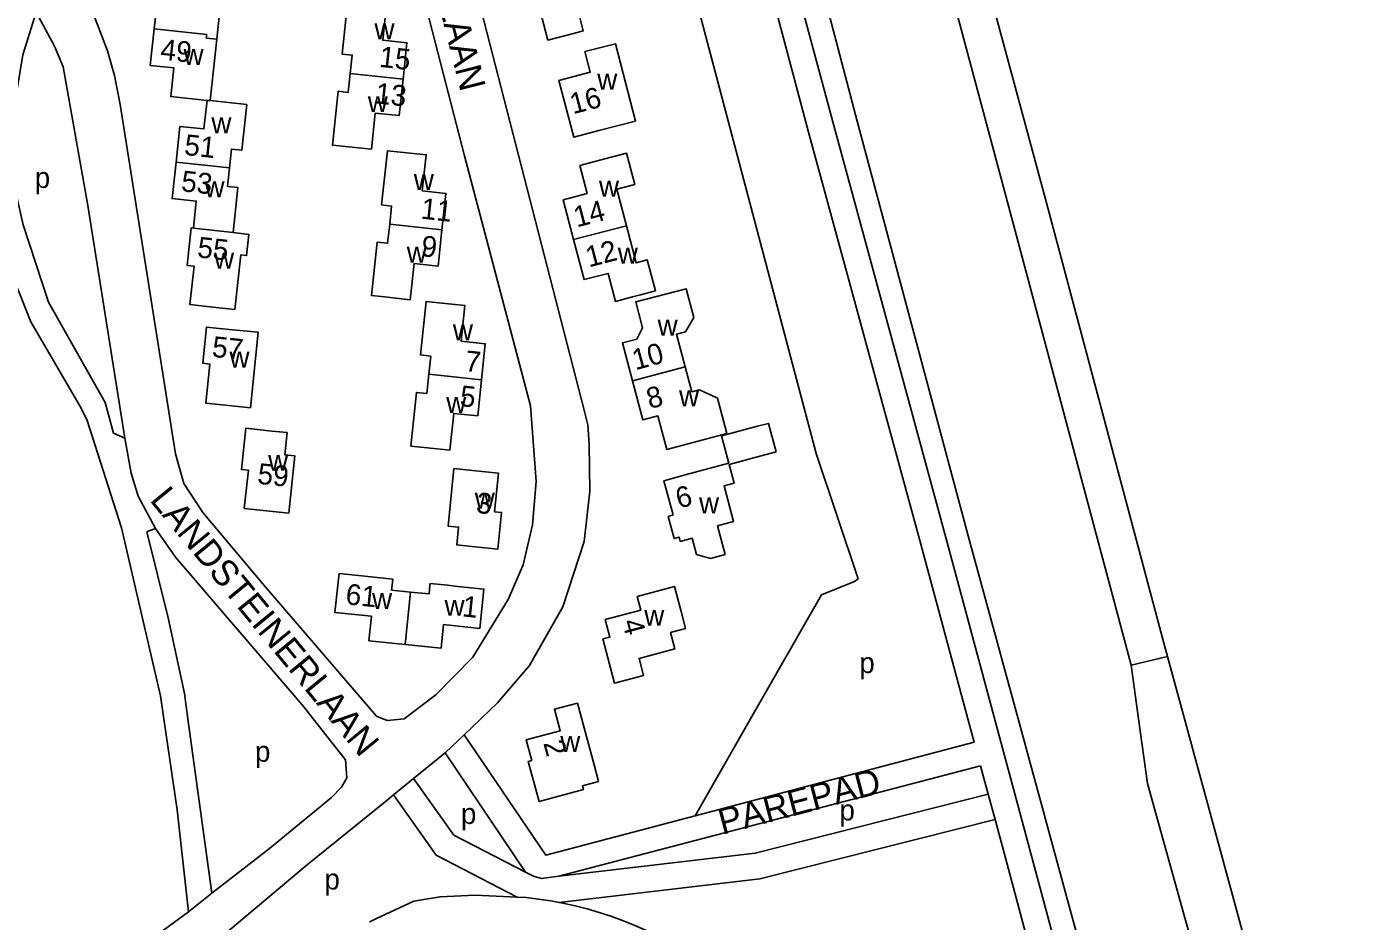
# Model space of a CAD drawing. Extents: x 161093 to 163177, y 379000 to 380904.
# Drawn here: x 162617.8 to 162872.7, y 380185.3 to 380357.5 of the extents above; entities that cross this region are included whole.
import ezdxf

# ---------------------------------------------------------------- set-up
doc = ezdxf.new("R2010")
doc.units = 0
for name, color, linetype in [('BLT_Basislijn', 7, 'Continuous'), ('BLT_Bebouwing', 7, 'Continuous'), ('BLT_Centroide', 7, 'Continuous'), ('BLT_Huisnummer', 7, 'Continuous'), ('BLT_Onderverdeling_panden', 7, 'Continuous'), ('BLT_Straatnaam', 7, 'Continuous'), ('BLT_Vlakafsluiter', 7, 'Continuous')]:
    doc.layers.add(name, color=color, linetype=linetype)

msp = doc.modelspace()

# ---------------------------------------------------------------- linework, layer by layer
at = {"layer": 'BLT_Basislijn'}
for p, q in [((162768.34, 380466.65), (162806.16, 380325.66)), ((162775.56, 380466.65), (162814.19, 380323.58)), ((162749.24, 380408.7), (162768.4, 380337.17)), ((162754.08, 380409.94), (162773.23, 380338.47)), ((162759.26, 380409.76), (162777.73, 380339.31)), ((162768.4, 380337.17), (162789.98, 380257.89)), ((162773.23, 380338.47), (162794.81, 380259.2)), ((162777.73, 380339.31), (162799.13, 380259.54)), ((162806.16, 380325.66), (162830.49, 380234.62)), ((162814.19, 380323.58), (162836.73, 380239.09)), ((162794.81, 380259.2), (162809.07, 380206.25)), ((162799.13, 380259.54), (162808.73, 380224.32)), ((162789.98, 380257.89), (162799.06, 380224.32)), ((162836.73, 380239.09), (162837.49, 380236.31)), ((162837.49, 380236.31), (162840.75, 380224.32)), ((162830.49, 380234.62), (162831.91, 380224.32)), ((162648.9, 380224.32), (162653.5, 380190.76)), ((162705.29, 380224.32), (162702.08, 380221.25)), ((162757.24, 380224.32), (162746.58, 380205.66)), ((162799.06, 380224.32), (162800.28, 380219.82)), ((162808.73, 380224.32), (162819.32, 380185.45)), ((162840.75, 380224.32), (162872.74, 380106.9)), ((162698.4, 380217.77), (162702.08, 380221.25)), ((162746.58, 380205.66), (162800.28, 380219.82)), ((162692.34, 380212.82), (162698.4, 380217.77)), ((162713.88, 380194.79), (162698.4, 380217.77)), ((162801.51, 380215.28), (162720.33, 380194)), ((162801.51, 380215.28), (162802.99, 380209.79)), ((162688.46, 380209.65), (162692.34, 380212.82)), ((162802.99, 380209.79), (162804.3, 380204.96)), ((162804.3, 380204.96), (162806.38, 380197.27)), ((162809.07, 380206.25), (162836.07, 380106.35)), ((162806.38, 380197.27), (162831.24, 380105.05)), ((162653.5, 380190.76), (162649, 380187.19)), ((162714, 380189.9), (162712.29, 380189.98)), ((162819.32, 380185.45), (162840.55, 380107.23))]:
    msp.add_line(p, q, dxfattribs=at)
for points in [[(162718.35, 380469.79), (162769.85, 380275.36), (162777.91, 380251.24), (162777.23, 380250.72), (162770.85, 380248.18), (162757.24, 380224.32)], [(162686.52, 380446.86), (162690.06, 380418.81), (162702.03, 380373.69), (162725.23, 380283.43), (162725.87, 380280.88), (162726.14, 380277.12), (162726.26, 380268.1), (162725.19, 380258.43), (162721.09, 380245.82), (162714.65, 380234.57), (162708.48, 380227.38), (162705.29, 380224.32)], [(162676.76, 380442.66), (162680.45, 380416.71), (162702.12, 380332.61), (162714.84, 380284.51), (162715.91, 380269.96), (162715.24, 380261.62), (162713.44, 380253.95), (162710.56, 380247.24), (162703.72, 380236.16), (162696.64, 380228.93), (162690.51, 380224.32)], [(162686.43, 380224.32), (162685.21, 380224.79), (162663.24, 380250.32), (162651.77, 380263.99), (162648.11, 380269.56), (162646.48, 380275.26), (162635.85, 380342.48), (162634.77, 380348.1), (162633.43, 380352.8), (162630.58, 380360.23), (162624.97, 380369.41), (162620.17, 380375.32), (162615.64, 380379.62), (162612.46, 380382.01)], [(162619.67, 380360.27), (162617.1, 380352.04), (162615.36, 380341.59), (162615.12, 380332.42), (162615.76, 380325.58), (162617.19, 380319.35), (162622.07, 380304.48), (162632.97, 380285.18), (162634.59, 380279.24), (162636.72, 380278.32)], [(162619.67, 380360.27), (162623.23, 380353.7), (162624.84, 380349.72), (162629.62, 380323.07), (162636.72, 380278.32)], [(162644.26, 380224.32), (162643.61, 380228.74), (162636.13, 380261.07), (162629.46, 380281.67), (162628.35, 380284.06), (162618.62, 380300.7), (162613.24, 380314.21)], [(162636.72, 380278.32), (162637.94, 380271.59), (162639.34, 380267.17), (162642.67, 380260.9)], [(162642.67, 380260.9), (162641.06, 380260.34), (162641.06, 380260.02), (162645.09, 380243.74), (162648.23, 380229.17), (162648.9, 380224.32)], [(162642.67, 380260.9), (162646.51, 380255.39), (162671.22, 380226.59), (162673, 380224.32)], [(162649, 380187.19), (162646.84, 380206.82), (162644.26, 380224.32)], [(162673, 380224.32), (162679.24, 380216.4), (162679.5, 380212.93), (162678.49, 380211.16), (162676.51, 380209.16), (162664.57, 380199.36), (162653.5, 380190.76)], [(162690.51, 380224.32), (162687.31, 380223.99), (162686.43, 380224.32)], [(162831.91, 380224.32), (162833.62, 380211.87), (162849.42, 380155.11), (162856.68, 380137.23), (162866, 380101.72)], [(162702.08, 380221.25), (162717.81, 380198.05), (162746.58, 380205.66)], [(162713.88, 380194.79), (162700.07, 380201.94), (162692.34, 380212.82)], [(162655.41, 380182.42), (162671.9, 380196.25), (162686.87, 380208.35), (162688.46, 380209.65)], [(162712.29, 380189.98), (162696.7, 380198.06), (162688.46, 380209.65)], [(162802.99, 380209.79), (162758.11, 380198.43), (162720.33, 380194)], [(162804.3, 380204.96), (162759.02, 380193.5), (162720.39, 380188.97)], [(162720.33, 380194), (162716.98, 380193.6), (162715.4, 380194), (162713.88, 380194.79)], [(162712.29, 380189.98), (162704.22, 380190.35), (162697.45, 380190.06), (162692.41, 380189.2), (162685.21, 380185.88), (162684.06, 380185.31), (162683.85, 380185.17)], [(162714, 380189.9), (162716.38, 380189.63), (162718.74, 380189.27), (162720.39, 380188.97)], [(162559.8, 380172.9), (162581.5, 380169.72), (162594.4, 380168.78), (162600, 380169.09), (162611.76, 380170.31), (162624.46, 380173.38), (162636.31, 380178.57), (162643.22, 380182.91), (162649, 380187.19)], [(162720.39, 380188.97), (162721.1, 380188.84), (162723.44, 380188.33), (162725.76, 380187.74), (162728.06, 380187.07), (162730.33, 380186.32), (162732.58, 380185.5), (162734.8, 380184.61), (162736.99, 380183.64), (162739.15, 380182.6), (162741.27, 380181.49), (162743.35, 380180.31), (162745.39, 380179.05), (162747.39, 380177.74), (162749.34, 380176.35), (162751.25, 380174.9), (162753.1, 380173.39), (162754.91, 380171.82), (162755.9, 380170.9)]]:
    msp.add_lwpolyline(points, dxfattribs=at)
at = {"layer": 'BLT_Bebouwing'}
msp.add_line((162652.57, 380343.27), (162653.17, 380343.24), dxfattribs=at)
for points in [[(162723.11, 380356.16), (162718.2, 380354.88), (162715.17, 380366.5), (162718.89, 380367.47), (162717.88, 380371.36), (162722.72, 380372.62), (162724.85, 380373.17), (162727.69, 380362.27), (162723.81, 380361.26), (162725.01, 380356.66), (162723.11, 380356.16)], [(162642.41, 380357.07), (162643.15, 380363.95), (162647.67, 380363.46), (162648.26, 380368.88), (162653.23, 380368.34), (162655.8, 380368.06), (162654.45, 380355.05)], [(162690.33, 380347.37), (162691.07, 380354.37), (162686.41, 380354.86), (162687.15, 380361.81), (162682.18, 380362.33), (162679.66, 380362.6), (162678.56, 380352.21), (162680.52, 380352), (162680.14, 380348.45)], [(162652.57, 380343.27), (162645.6, 380344.03), (162646.19, 380349.53), (162641.65, 380350.02), (162642.41, 380357.07)], [(162653.17, 380343.24), (162654.45, 380355.05)], [(162730.17, 380353.93), (162725.33, 380352.67), (162726.37, 380348.71), (162720.33, 380347.14), (162723.17, 380336.21), (162728.02, 380337.47), (162735.06, 380339.3), (162731.19, 380354.2), (162730.17, 380353.93)], [(162680.14, 380348.45), (162679.76, 380344.83), (162677.81, 380345.04), (162676.71, 380334.69), (162679.25, 380334.42), (162684.22, 380333.89), (162684.96, 380340.86), (162689.58, 380340.37), (162690.33, 380347.37)], [(162646.61, 380331.43), (162647.36, 380338.29), (162651.97, 380337.79), (162652.57, 380343.27)], [(162656.88, 380330.32), (162657.27, 380333.91), (162659.26, 380333.7), (162660.21, 380342.47), (162653.17, 380343.24)], [(162697.81, 380318.4), (162698.58, 380325.39), (162694.02, 380325.89), (162694.77, 380332.82), (162689.8, 380333.36), (162687.32, 380333.59), (162686.17, 380323.18), (162688.12, 380322.96), (162687.74, 380319.49)], [(162723.16, 380316.5), (162721.15, 380324.19), (162725.75, 380325.4), (162724.35, 380330.75), (162729.19, 380332.02), (162733.35, 380333.11), (162734.91, 380327.13), (162731.47, 380326.23), (162733.32, 380319.16)], [(162649.94, 380318.72), (162650.5, 380323.91), (162645.85, 380324.41), (162646.61, 380331.43)], [(162657.58, 380317.89), (162658.51, 380326.51), (162656.49, 380326.73), (162656.88, 380330.32)], [(162687.74, 380319.49), (162687.34, 380315.8), (162685.35, 380316.02), (162684.23, 380305.76), (162686.73, 380305.49), (162691.7, 380304.94), (162692.45, 380311.9), (162697.05, 380311.4), (162697.81, 380318.4)], [(162738.91, 380306.62), (162737.34, 380312.62), (162735.18, 380312.05), (162733.32, 380319.16)], [(162657.58, 380317.89), (162660.65, 380317.49), (162660.2, 380313.43), (162659.06, 380313.55), (162657.93, 380303.06), (162654.25, 380303.46), (162649.28, 380303.99), (162650.08, 380311.4), (162648.73, 380311.55), (162649.52, 380318.77), (162649.94, 380318.72)], [(162734.5, 380305.47), (162731.2, 380304.6), (162729.79, 380310.01), (162725.17, 380308.8), (162723.16, 380316.5)], [(162744.63, 380292.03), (162742.95, 380298.31), (162744.67, 380298.77), (162746.27, 380301.49), (162744.8, 380307.06), (162735.12, 380304.52), (162736.44, 380299.5), (162735.31, 380297.37), (162732.54, 380296.63), (162734.48, 380289.35)], [(162738.91, 380306.62), (162736.05, 380305.87), (162734.5, 380305.47)], [(162705.41, 380289.54), (162706.14, 380296.48), (162701.48, 380296.97), (162702.2, 380303.86), (162697.23, 380304.37), (162694.74, 380304.6), (162693.66, 380294.31), (162695.64, 380294.1), (162695.27, 380290.59)], [(162657.47, 380299.17), (162652.46, 380299.68), (162651.74, 380292.71), (162653.11, 380292.57), (162652.35, 380285.01), (162657.32, 380284.51), (162660.93, 380284.14), (162662.4, 380298.67)], [(162662.4, 380298.67), (162657.47, 380299.17)], [(162734.48, 380289.35), (162736.48, 380281.81), (162739.38, 380282.58), (162741.1, 380276.14), (162752.64, 380279.2), (162750.84, 380286.02), (162747.36, 380287.61), (162745.92, 380287.22), (162744.63, 380292.03)], [(162695.27, 380290.59), (162694.89, 380286.91), (162692.9, 380287.11), (162691.83, 380276.78), (162694.36, 380276.52), (162699.33, 380276), (162700.07, 380283.08), (162704.69, 380282.6), (162705.41, 380289.54)], [(162752.35, 380255.92), (162750.86, 380261.42), (162753.96, 380262.26), (162752.11, 380269.1), (162754.06, 380269.63), (162753.09, 380273.23), (162760, 380275.09), (162762.14, 380275.67), (162760.66, 380281.15), (162758.53, 380280.58), (162751.63, 380278.72), (162753.02, 380273.49)], [(162668.84, 380268.84), (162669.48, 380274.89), (162667.52, 380275.1), (162667.98, 380279.37), (162665.02, 380279.68), (162660.03, 380280.22), (162659.18, 380272.29), (162660.54, 380272.14), (162659.75, 380264.78), (162668.31, 380263.86), (162668.84, 380268.84)], [(162753.02, 380273.49), (162745.35, 380271.42), (162740.52, 380270.11), (162742.31, 380263.52), (162741.33, 380263.26), (162742.49, 380258.99), (162743.47, 380259.26), (162743.69, 380258.44), (162745.96, 380259.06), (162746.81, 380255.89), (162749.54, 380255.17), (162752.35, 380255.92)], [(162703.7, 380272.08), (162700.11, 380272.44), (162698.97, 380261.39), (162701, 380261.18), (162700.65, 380257.75), (162703.58, 380257.45), (162708.55, 380256.93), (162709.28, 380264), (162707.91, 380264.14), (162708.67, 380271.57), (162703.7, 380272.08)], [(162691.75, 380248.7), (162688.12, 380249.08), (162688.2, 380250), (162688.33, 380251.17), (162682.98, 380251.73), (162677.99, 380252.25), (162677.76, 380250), (162677.2, 380244.78), (162684.23, 380244.05), (162683.74, 380239.32), (162690.7, 380238.59)], [(162691.75, 380248.7), (162695.33, 380248.33), (162695.5, 380250), (162695.54, 380250.35), (162698.86, 380250), (162700.89, 380249.79), (162705.87, 380249.26), (162705.08, 380241.7), (162698.13, 380242.43), (162697.65, 380237.87), (162690.7, 380238.59)], [(162743.87, 380244.93), (162744.72, 380241.71), (162741.82, 380240.94), (162742.66, 380237.76), (162735.76, 380235.93), (162736.63, 380232.62), (162731.05, 380231.15), (162730.07, 380234.85), (162728.79, 380239.68), (162730.14, 380240.04), (162729.25, 380243.43), (162736.07, 380245.24), (162735.38, 380247.86), (162742.59, 380249.77), (162743.87, 380244.93)], [(162723.9, 380227.33), (162719.45, 380226.13), (162720.57, 380222.02), (162714.03, 380220.25), (162715.1, 380216.3), (162714.39, 380216.1), (162716.49, 380208.37), (162725.05, 380210.69), (162724.86, 380211.39), (162727.94, 380212.22), (162727.13, 380215.42), (162723.9, 380227.33)]]:
    msp.add_lwpolyline(points, dxfattribs=at)
at = {"layer": 'BLT_Onderverdeling_panden'}
for p, q in [((162690.33, 380347.37), (162680.14, 380348.45)), ((162656.88, 380330.32), (162646.61, 380331.43)), ((162697.81, 380318.4), (162687.74, 380319.49)), ((162723.16, 380316.5), (162733.32, 380319.16)), ((162657.58, 380317.89), (162649.94, 380318.72)), ((162734.48, 380289.35), (162744.63, 380292.03)), ((162705.41, 380289.54), (162695.27, 380290.59)), ((162690.7, 380238.59), (162691.75, 380248.7))]:
    msp.add_line(p, q, dxfattribs=at)
for points in [[(162652.51, 380355.99), (162642.41, 380357.07)], [(162654.45, 380355.05), (162652.43, 380355.27), (162652.51, 380355.99)]]:
    msp.add_lwpolyline(points, dxfattribs=at)
at = {"layer": 'BLT_Vlakafsluiter'}
msp.add_line((162830.49, 380234.62), (162837.49, 380236.31), dxfattribs=at)

# ---------------------------------------------------------------- texts
at = {"layer": 'BLT_Centroide'}
for s, p in [('w', (162684.81, 380355.02)), ('w', (162648.05, 380350.11)), ('w', (162727.7, 380345.33)), ('w', (162683.52, 380341.03)), ('w', (162653.41, 380336.95)), ('p', (162619.4, 380326.44)), ('w', (162652.09, 380324.66)), ('w', (162692.38, 380326.03)), ('w', (162728.03, 380324.75)), ('w', (162691.02, 380312.08)), ('w', (162731.66, 380311.88)), ('w', (162653.92, 380310.89)), ('w', (162699.91, 380297.11)), ('w', (162739.33, 380298.02)), ('w', (162656.89, 380291.89)), ('w', (162698.62, 380283.16)), ('w', (162743.45, 380284.44)), ('w', (162664.33, 380272.02)), ('w', (162704.12, 380264.72)), ('w', (162747.3, 380263.84)), ('w', (162684.34, 380245.41)), ('w', (162698.3, 380244.12)), ('w', (162736.75, 380242.2)), ('p', (162778.16, 380233.09)), ('w', (162720.58, 380217.95)), ('p', (162661.8, 380216.03)), ('p', (162701.45, 380204.07)), ('p', (162774.33, 380204.75)), ('p', (162675.18, 380191.46))]:
    msp.add_text(s, height=4, dxfattribs=at).set_placement(p)
at = {"layer": 'BLT_Huisnummer'}
for s, rotation, p in [('49', 353.8186, (162643.47, 380351.18)), ('15', 353.9354, (162685.61, 380349.76)), ('13', 353.9382, (162684.83, 380342.74)), ('16', 14.5833, (162723.03, 380340.61)), ('51', 353.8075, (162648.07, 380332.82)), ('53', 353.8146, (162647.46, 380325.84)), ('11', 353.7785, (162693.62, 380320.56)), ('14', 14.6633, (162723.75, 380318.83)), ('55', 353.8231, (162650.58, 380313.1)), ('9', 353.7762, (162693.67, 380313.35)), ('12', 14.6656, (162726.09, 380311.14)), ('57', 354.2153, (162653.42, 380293.96)), ('10', 15.0596, (162735.05, 380291.36)), ('7', 354.0651, (162702.1, 380291.22)), ('5', 354.0648, (162701.13, 380284.5)), ('8', 15.0497, (162737.8, 380283.89)), ('59', 353.8966, (162662.15, 380269.55)), ('6', 15.144, (162743.42, 380264.72)), ('3', 354.1104, (162704.26, 380263.94)), ('61', 354.058, (162679.13, 380246.36)), ('1', 354.061, (162701.58, 380244.03)), ('4', 284.8118, (162732.45, 380243)), ('2', 285.1459, (162717.29, 380219.66))]:
    msp.add_text(s, height=4, rotation=rotation, dxfattribs=at).set_placement(p)
at = {"layer": 'BLT_Straatnaam'}
for s, rotation, p in [('SCHWEITZERLAAN', 284.1212, (162686.39, 380404.54)), ('LANDSTEINERLAAN', 309.3947, (162641.4, 380266.35)), ('PAREPAD', 14.7359, (162751.77, 380201.97))]:
    msp.add_text(s, height=5, rotation=rotation, dxfattribs=at).set_placement(p)

doc.saveas('drawing.dxf')
